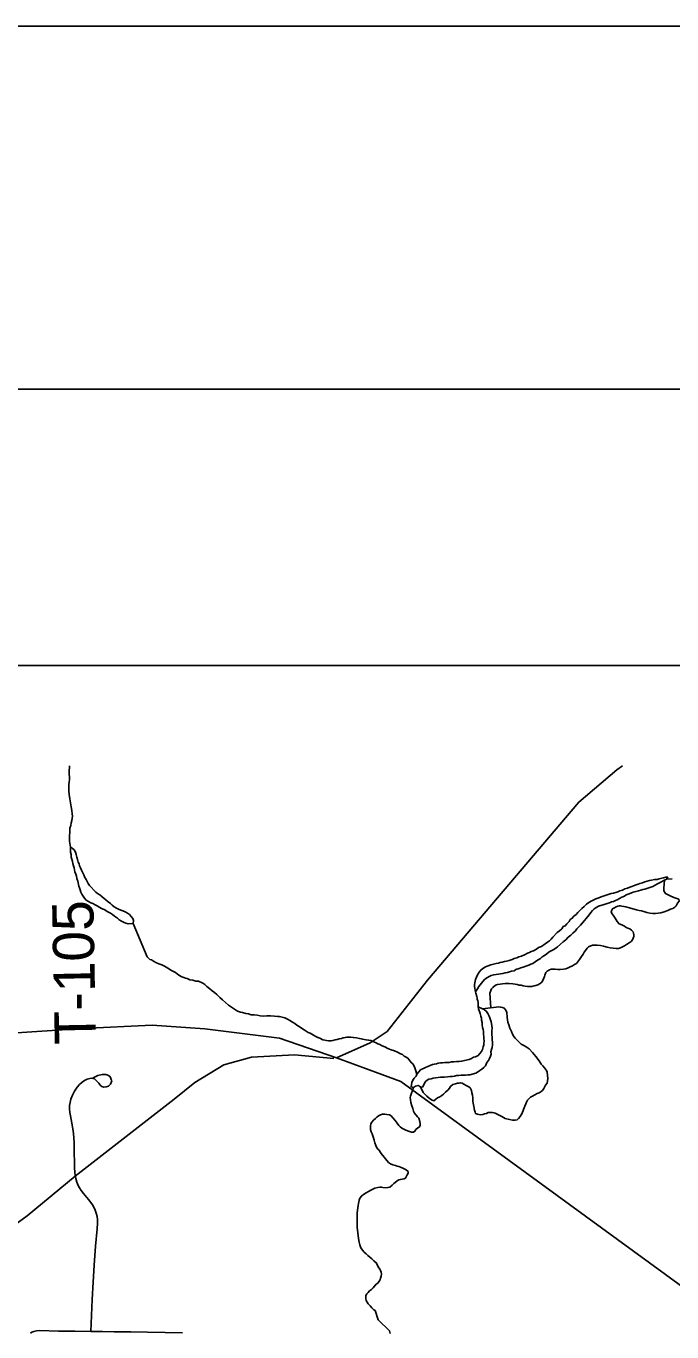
# Model space of a CAD drawing. Extents: x -11.4 to 84.1, y 11.1 to 59.
# Drawn here: x 30.669 to 31.559, y 46.631 to 48.429 of the extents above; entities that cross this region are included whole.
import ezdxf

# ---------------------------------------------------------------- set-up
doc = ezdxf.new("R2010")
doc.units = 0
for name, color, linetype in [('GM_X_Major_River', 7, 'Continuous'), ('GM_X_Minor_Lake', 7, 'Continuous'), ('GM_X_Minor_River', 7, 'Continuous'), ('GM_X_Rail_Line', 7, 'Continuous'), ('GM_X_Township_Road', 7, 'Continuous'), ('GM_X_Township_Road_Text', 7, 'Continuous'), ('SH_Border', 7, 'Continuous'), ('SH_Cut_Line', 7, 'Continuous'), ('SH_Data', 7, 'Continuous')]:
    doc.layers.add(name, color=color, linetype=linetype)

msp = doc.modelspace()

# ---------------------------------------------------------------- linework, layer by layer
at = {"layer": 'GM_X_Major_River'}
for points in [[(31.5511, 47.2539), (31.5529, 47.2566), (31.5503, 47.2566), (31.5473, 47.2558), (31.5446, 47.2554), (31.5412, 47.2546), (31.5382, 47.2538), (31.5348, 47.2534), (31.5306, 47.2527), (31.5276, 47.2523), (31.5246, 47.2511), (31.5215, 47.2503), (31.5181, 47.2488), (31.5147, 47.248), (31.5121, 47.2472), (31.5094, 47.2461), (31.506, 47.2449), (31.5034, 47.2441), (31.5007, 47.243), (31.4973, 47.2418), (31.4939, 47.2406), (31.4905, 47.2391), (31.4871, 47.2379), (31.4841, 47.2368), (31.4815, 47.2356), (31.4784, 47.2348), (31.475, 47.2341), (31.4724, 47.2333), (31.4694, 47.2325), (31.4626, 47.2302), (31.4565, 47.2279), (31.4539, 47.2271), (31.4512, 47.2255), (31.4486, 47.2244), (31.4444, 47.2217), (31.441, 47.2194), (31.4377, 47.2163), (31.4346, 47.2137), (31.4316, 47.2106), (31.429, 47.2083), (31.4267, 47.2056), (31.4237, 47.2033), (31.4215, 47.2003), (31.4185, 47.1984), (31.417, 47.1957), (31.4139, 47.1927), (31.4117, 47.19), (31.409, 47.1888), (31.4072, 47.1858), (31.4038, 47.1831), (31.4008, 47.1804), (31.3947, 47.1743), (31.3925, 47.1716), (31.3899, 47.1693), (31.3872, 47.1674), (31.3842, 47.1651), (31.3789, 47.1613), (31.3751, 47.1598), (31.3721, 47.1578), (31.368, 47.1555), (31.365, 47.1544), (31.3623, 47.1532), (31.3597, 47.1521), (31.3566, 47.1505), (31.3514, 47.1482), (31.348, 47.147), (31.3453, 47.1459), (31.3415, 47.1447), (31.3385, 47.1436), (31.3344, 47.142), (31.3309, 47.1412), (31.3283, 47.1405), (31.3249, 47.1397), (31.3222, 47.1393), (31.3196, 47.1385), (31.3166, 47.1377), (31.3128, 47.1369), (31.3094, 47.1362), (31.3018, 47.1331), (31.2984, 47.1311), (31.2954, 47.1288), (31.2932, 47.1262), (31.2909, 47.1224), (31.2894, 47.1189), (31.2883, 47.1159), (31.2868, 47.1091), (31.2869, 47.1064), (31.2882, 47.0987)], [(31.5019, 47.2346), (31.5053, 47.2362), (31.5091, 47.2369), (31.5125, 47.2381), (31.5159, 47.2389), (31.5186, 47.2397), (31.5212, 47.2404), (31.5254, 47.2416), (31.5322, 47.2439), (31.5356, 47.2459), (31.539, 47.2474), (31.5416, 47.2489), (31.5484, 47.2528), (31.5511, 47.2539)], [(31.5511, 47.2539), (31.559, 47.2544)], [(31.2882, 47.0987), (31.291, 47.103), (31.2929, 47.1064), (31.2982, 47.1133), (31.3012, 47.1164), (31.3046, 47.1187), (31.3072, 47.1202), (31.3099, 47.1214), (31.3133, 47.1225), (31.3167, 47.1229), (31.3258, 47.1241), (31.3288, 47.1249), (31.3322, 47.1257), (31.3348, 47.1265), (31.3379, 47.1272), (31.3413, 47.128), (31.3439, 47.1296), (31.3481, 47.1311), (31.3507, 47.1319), (31.3537, 47.1327), (31.359, 47.1346), (31.3617, 47.1354), (31.3643, 47.1369), (31.367, 47.1381), (31.3704, 47.14), (31.3737, 47.1427), (31.3775, 47.145), (31.3802, 47.1473), (31.3832, 47.1488), (31.3866, 47.1511), (31.3896, 47.1538), (31.3949, 47.1569), (31.3986, 47.1588), (31.4013, 47.1607), (31.4088, 47.1676), (31.4126, 47.1706), (31.416, 47.1741), (31.4194, 47.1768), (31.4224, 47.1798), (31.4261, 47.1829), (31.4276, 47.1855), (31.4303, 47.1882), (31.4329, 47.1909), (31.4355, 47.1939), (31.4385, 47.197), (31.4408, 47.1997), (31.4445, 47.205), (31.4468, 47.2081), (31.4491, 47.2107), (31.4517, 47.2134), (31.4551, 47.2157), (31.4577, 47.2169), (31.4653, 47.2192), (31.4695, 47.2204), (31.4729, 47.2215), (31.4755, 47.2227), (31.4781, 47.2231)], [(31.4781, 47.2231), (31.4808, 47.2246), (31.4834, 47.2258), (31.4865, 47.2273), (31.4895, 47.2292), (31.4932, 47.2308), (31.4959, 47.2323), (31.4985, 47.2335), (31.5019, 47.2346)], [(31.2882, 47.0987), (31.2884, 47.0969), (31.29, 47.0924), (31.2904, 47.0905), (31.2904, 47.0886), (31.2912, 47.0863), (31.2916, 47.0844), (31.2916, 47.0825), (31.2917, 47.0784)], [(31.2917, 47.0784), (31.2924, 47.0757), (31.2947, 47.0689), (31.2955, 47.0655), (31.2962, 47.0628), (31.2966, 47.0598), (31.2974, 47.0568), (31.2975, 47.0533), (31.2979, 47.0496), (31.2986, 47.0469), (31.299, 47.0442), (31.2991, 47.0405), (31.2995, 47.037), (31.2998, 47.0344), (31.2999, 47.031), (31.2995, 47.0283), (31.2995, 47.0257), (31.2988, 47.023), (31.2977, 47.0196), (31.2962, 47.0169), (31.2943, 47.0139), (31.2917, 47.0112), (31.2883, 47.0096), (31.2856, 47.0089), (31.2826, 47.0073), (31.2792, 47.0058)], [(31.3088, 47.0603), (31.308, 47.0629), (31.3068, 47.0656), (31.3053, 47.069), (31.3034, 47.072), (31.3003, 47.0746), (31.2977, 47.0757), (31.2917, 47.0784)], [(31.2029, 46.9673), (31.2056, 46.9692), (31.209, 46.97), (31.2124, 46.9681), (31.2151, 46.9678), (31.2169, 46.9708), (31.2184, 46.9739), (31.2203, 46.9765), (31.2237, 46.9785), (31.2271, 46.9792), (31.2298, 46.98), (31.24, 46.9812), (31.2426, 46.9812), (31.2453, 46.9816), (31.2494, 46.982), (31.2528, 46.9825), (31.2566, 46.9825), (31.2593, 46.9829), (31.2619, 46.9837), (31.265, 46.9837), (31.2684, 46.9841), (31.2744, 46.9841), (31.2778, 46.9845), (31.2805, 46.9845), (31.2884, 46.9869), (31.2911, 46.9884), (31.2941, 46.9907), (31.2967, 46.9926), (31.2994, 46.9949), (31.302, 46.9972), (31.3039, 47.0014), (31.3061, 47.0041), (31.3076, 47.0071), (31.3087, 47.0105), (31.3095, 47.0132), (31.3094, 47.0162), (31.3102, 47.0197), (31.3109, 47.0223), (31.3117, 47.0261), (31.3116, 47.0295), (31.3112, 47.0329), (31.3112, 47.0364), (31.3108, 47.0398), (31.3108, 47.0432), (31.3108, 47.0458), (31.3111, 47.0485), (31.3107, 47.0523), (31.3099, 47.0576), (31.3088, 47.0603)], [(31.2792, 47.0058), (31.269, 47.0034), (31.2656, 47.003), (31.2622, 47.003), (31.2584, 47.0026), (31.255, 47.0026), (31.252, 47.0018), (31.2493, 47.0014), (31.2459, 47.0014), (31.2429, 47.001), (31.2398, 47.001), (31.2368, 47.0006), (31.2342, 46.9998), (31.2315, 46.9994), (31.2289, 46.9986), (31.2258, 46.9974), (31.2232, 46.9967), (31.2194, 46.9947), (31.2126, 46.9913), (31.21, 46.9886), (31.2074, 46.9856), (31.2062, 46.9829), (31.2036, 46.9798), (31.2017, 46.9772), (31.2006, 46.9741), (31.1999, 46.9715), (31.1995, 46.968), (31.2029, 46.9673)], [(31.1523, 46.9265), (31.1545, 46.9281), (31.1572, 46.9296), (31.1602, 46.9304), (31.1632, 46.9304), (31.1659, 46.9301), (31.1697, 46.9294), (31.172, 46.9279), (31.1743, 46.9252), (31.1774, 46.9215), (31.1801, 46.9181), (31.1824, 46.915), (31.1844, 46.9132), (31.1867, 46.9113), (31.1893, 46.9098), (31.1924, 46.9083), (31.1958, 46.9068), (31.2, 46.9057), (31.2027, 46.9057), (31.2046, 46.9069), (31.2061, 46.9092), (31.2087, 46.9115), (31.2106, 46.9127), (31.2117, 46.915), (31.2117, 46.9169), (31.2113, 46.9203), (31.2101, 46.9248), (31.2081, 46.9267), (31.2043, 46.932), (31.2027, 46.9346), (31.2016, 46.938), (31.2004, 46.9418), (31.1992, 46.9464), (31.1984, 46.9502), (31.198, 46.9532), (31.1987, 46.9551), (31.2029, 46.9673)], [(31.154, 46.6474), (31.15, 46.66), (31.1481, 46.6611), (31.1454, 46.6637), (31.1431, 46.6664), (31.1404, 46.669), (31.1389, 46.6713), (31.1377, 46.6739), (31.1373, 46.6766), (31.1369, 46.6785), (31.1372, 46.6808), (31.1384, 46.6831), (31.1402, 46.685), (31.1421, 46.6869), (31.1448, 46.6888), (31.1474, 46.6911), (31.1515, 46.6961), (31.1534, 46.6977), (31.1553, 46.7003), (31.1568, 46.7023), (31.1575, 46.7045), (31.1582, 46.7072), (31.1586, 46.7099), (31.1582, 46.7129), (31.1574, 46.7152), (31.1562, 46.7171), (31.1539, 46.7201), (31.1519, 46.7254), (31.1481, 46.7284), (31.1454, 46.7314), (31.1427, 46.7337), (31.14, 46.7359), (31.1377, 46.7382), (31.135, 46.7404), (31.1327, 46.7431), (31.1304, 46.7465), (31.1288, 46.7503), (31.1277, 46.754), (31.1268, 46.759), (31.1251, 46.7749), (31.1253, 46.7943), (31.1256, 46.7981), (31.1267, 46.8046), (31.127, 46.8073), (31.1274, 46.8096), (31.1281, 46.8122), (31.1289, 46.8149), (31.1315, 46.818), (31.1341, 46.8199), (31.1375, 46.8222), (31.1409, 46.8241), (31.1451, 46.8261), (31.1496, 46.8284), (31.1538, 46.8296), (31.1564, 46.83), (31.1583, 46.83), (31.1606, 46.8293), (31.1644, 46.8289), (31.1675, 46.8293), (31.1701, 46.8301), (31.1735, 46.8328), (31.1758, 46.8351), (31.1776, 46.8363), (31.1803, 46.8386), (31.1825, 46.8398), (31.1848, 46.8405), (31.1871, 46.8409), (31.1897, 46.8414), (31.1916, 46.8425), (31.1939, 46.8467), (31.1954, 46.849), (31.1953, 46.8513), (31.1926, 46.8539), (31.1881, 46.8562), (31.185, 46.8573), (31.1827, 46.8584), (31.1804, 46.8588), (31.1778, 46.8595), (31.1743, 46.8606), (31.1709, 46.8621), (31.1682, 46.864), (31.1582, 46.8764), (31.1551, 46.8813), (31.1528, 46.8832), (31.1508, 46.8874), (31.1496, 46.8908), (31.1485, 46.8946), (31.1473, 46.8991), (31.1457, 46.9033), (31.1445, 46.9063), (31.1437, 46.9093), (31.1437, 46.912), (31.1437, 46.9143), (31.144, 46.9173), (31.1455, 46.9196), (31.1478, 46.9223), (31.1504, 46.9246), (31.1523, 46.9265)], [(31.1704, 46.6283), (31.1696, 46.6321), (31.154, 46.6474)]]:
    msp.add_lwpolyline(points, dxfattribs=at)
at = {"layer": 'GM_X_Minor_Lake'}
for points in [[(30.7302, 47.2991), (30.7302, 47.298), (30.7302, 47.2912), (30.731, 47.2878), (30.7314, 47.2844), (30.7322, 47.2817), (30.7329, 47.2783), (30.7337, 47.2757), (30.7345, 47.2723), (30.7353, 47.2696), (30.7357, 47.267), (30.7364, 47.2643), (30.7376, 47.2609), (30.7384, 47.2582), (30.7392, 47.2548), (30.7403, 47.2514), (30.7419, 47.2446), (30.7427, 47.242), (30.7438, 47.2393), (30.7446, 47.2363), (30.7461, 47.2336), (30.7477, 47.2306), (30.7496, 47.228), (30.7519, 47.2253), (30.7553, 47.2234), (30.7583, 47.2216), (30.761, 47.2205), (30.7644, 47.2186), (30.7671, 47.2171), (30.7705, 47.2152), (30.7732, 47.2137), (30.7766, 47.2122), (30.7819, 47.2092), (30.7853, 47.207), (30.788, 47.2055), (30.7907, 47.2032), (30.7948, 47.2002), (30.7975, 47.1979), (30.8006, 47.1964), (30.804, 47.1946), (30.8066, 47.1934), (30.8097, 47.1927), (30.8168, 47.1928)], [(30.7652, 47.236), (30.7563, 47.2455), (30.7544, 47.2481), (30.7532, 47.2508), (30.7517, 47.2538), (30.7498, 47.2564), (30.7486, 47.2602), (30.7455, 47.2663), (30.744, 47.2697), (30.7428, 47.2723), (30.7421, 47.275), (30.7409, 47.2776), (30.7401, 47.281), (30.739, 47.2844), (30.7382, 47.2878), (30.737, 47.2913), (30.7355, 47.2943), (30.7324, 47.2969), (30.7302, 47.2991)], [(30.8168, 47.1928), (30.8172, 47.1969), (30.8161, 47.2), (30.8138, 47.2026), (30.8115, 47.2056), (30.8088, 47.2071), (30.8058, 47.209), (30.8024, 47.2105), (30.7997, 47.2112), (30.7963, 47.2127), (30.7936, 47.2142), (30.7906, 47.2161), (30.7879, 47.2184), (30.7852, 47.2206), (30.7822, 47.2229), (30.7791, 47.2255), (30.7765, 47.2274), (30.7738, 47.2296), (30.7708, 47.2323), (30.7673, 47.2342), (30.7652, 47.236)]]:
    msp.add_lwpolyline(points, dxfattribs=at)
at = {"layer": 'GM_X_Minor_River'}
for points in [[(30.7289, 47.4103), (30.7289, 47.4082), (30.7286, 47.4033), (30.7286, 47.3987)], [(30.7286, 47.3987), (30.7287, 47.3945), (30.7287, 47.3911), (30.7284, 47.3877), (30.728, 47.3843), (30.7281, 47.3804), (30.7281, 47.3759), (30.7286, 47.3706), (30.7294, 47.3645), (30.7302, 47.3592), (30.7311, 47.3535), (30.7319, 47.3485), (30.7327, 47.344), (30.7331, 47.3406), (30.7328, 47.3379), (30.732, 47.3349), (30.7313, 47.3314), (30.7306, 47.328), (30.7295, 47.3242), (30.7292, 47.3211), (30.7292, 47.3181), (30.7289, 47.3135), (30.7289, 47.309), (30.7289, 47.3063), (30.7302, 47.298)], [(31.5322, 47.2067), (31.536, 47.2068), (31.5398, 47.2072), (31.5436, 47.2076), (31.5478, 47.2091), (31.5531, 47.2107), (31.5568, 47.2127), (31.5599, 47.2138), (31.5625, 47.2154), (31.5644, 47.2173), (31.5655, 47.2192), (31.5666, 47.2211), (31.5685, 47.2238), (31.5681, 47.2265), (31.5654, 47.2272), (31.5612, 47.2287), (31.5563, 47.2309), (31.5524, 47.2328), (31.5498, 47.2343), (31.5474, 47.238), (31.5474, 47.2399), (31.5474, 47.2418), (31.5484, 47.2528)], [(31.3094, 47.0768), (31.3081, 47.0969), (31.3091, 47.1007), (31.3103, 47.103), (31.3118, 47.1049), (31.3155, 47.108), (31.3186, 47.1092), (31.3292, 47.1104), (31.3345, 47.1105), (31.3395, 47.1101), (31.3429, 47.1094), (31.3455, 47.109), (31.3482, 47.1083), (31.3509, 47.108), (31.3539, 47.1072), (31.3566, 47.1065), (31.3596, 47.1061), (31.3627, 47.1062), (31.3657, 47.1062), (31.3688, 47.107), (31.3714, 47.1074), (31.3741, 47.1086), (31.3771, 47.1105), (31.3793, 47.1124), (31.3808, 47.1143), (31.3819, 47.117), (31.3831, 47.1201), (31.3838, 47.122), (31.3849, 47.1254), (31.3868, 47.1273), (31.3902, 47.1293), (31.3924, 47.13), (31.3947, 47.1301), (31.3981, 47.1301), (31.4016, 47.1298), (31.4046, 47.1298), (31.4092, 47.1302), (31.4126, 47.1306), (31.4156, 47.1318), (31.4186, 47.1333), (31.4217, 47.1349), (31.4247, 47.1364), (31.4273, 47.138), (31.4314, 47.1434), (31.4341, 47.1476), (31.4363, 47.1506), (31.4378, 47.1537), (31.4397, 47.156), (31.4419, 47.159), (31.4438, 47.161), (31.4491, 47.1633), (31.4521, 47.1633), (31.4559, 47.163), (31.4601, 47.1627), (31.4643, 47.1619), (31.4696, 47.1605), (31.4738, 47.1594), (31.478, 47.159), (31.4818, 47.1587), (31.4852, 47.1587), (31.4879, 47.1595), (31.4905, 47.1607), (31.4936, 47.1622), (31.4962, 47.1642), (31.4996, 47.1665), (31.5026, 47.1684), (31.5045, 47.1703), (31.5063, 47.1749), (31.5063, 47.1776), (31.5059, 47.1798), (31.5051, 47.1817), (31.5032, 47.184), (31.5009, 47.1855), (31.4982, 47.1866), (31.4959, 47.1877), (31.4933, 47.1892), (31.4898, 47.1911), (31.486, 47.1926), (31.4833, 47.1956), (31.4806, 47.2005), (31.4779, 47.2043), (31.4759, 47.2069), (31.4748, 47.2092), (31.4759, 47.2115), (31.477, 47.2134), (31.4789, 47.2142), (31.4819, 47.2161), (31.4842, 47.2169), (31.4861, 47.2173), (31.488, 47.2173), (31.4899, 47.2169), (31.4926, 47.2166), (31.4952, 47.2158), (31.4983, 47.2151), (31.5101, 47.2118), (31.5135, 47.2111), (31.5166, 47.2104), (31.52, 47.2093), (31.5242, 47.2082), (31.5284, 47.2074), (31.5322, 47.2067)], [(30.8168, 47.1928), (30.8361, 47.1469), (30.8396, 47.1436), (30.8418, 47.1428), (30.8445, 47.1413), (30.8476, 47.1394), (30.8518, 47.1376), (30.856, 47.1361), (30.8598, 47.1342), (30.8644, 47.1316), (30.8694, 47.1283), (30.8747, 47.1253), (30.8797, 47.1219), (30.8835, 47.1197), (30.8862, 47.1185), (30.8885, 47.1178), (30.8908, 47.1171), (30.8946, 47.1156), (30.8988, 47.1149), (30.903, 47.1138), (30.9068, 47.1134), (30.9125, 47.1108), (30.9152, 47.1089), (30.9179, 47.1063), (30.9221, 47.1029), (30.9256, 47.1003), (30.9287, 47.0981), (30.9317, 47.095), (30.936, 47.0913), (30.9398, 47.0879), (30.9436, 47.0841), (30.9479, 47.0804), (30.9521, 47.0778), (30.9548, 47.0759), (30.9574, 47.074), (30.9605, 47.0721), (30.9643, 47.071), (30.9674, 47.0703), (30.9716, 47.0692), (30.9754, 47.0685), (30.9792, 47.0674), (30.9834, 47.067), (30.9876, 47.0667), (30.9917, 47.066), (30.9963, 47.0656), (31.0009, 47.0657), (31.0058, 47.0657), (31.0115, 47.0654), (31.0153, 47.0651), (31.018, 47.0647), (31.0218, 47.064), (31.0256, 47.0629), (31.0291, 47.0614), (31.0325, 47.0595), (31.0359, 47.0573), (31.0394, 47.0551), (31.0421, 47.0532), (31.0444, 47.0517), (31.0478, 47.0494), (31.0497, 47.0479), (31.052, 47.0464), (31.0547, 47.0446), (31.0578, 47.0431), (31.0605, 47.042), (31.0627, 47.0408), (31.065, 47.0393), (31.0681, 47.0375), (31.0708, 47.036), (31.0738, 47.0349), (31.078, 47.033), (31.0857, 47.0312), (31.0876, 47.0312), (31.0895, 47.0316), (31.0917, 47.032), (31.0948, 47.0328), (31.0974, 47.0332), (31.1005, 47.034), (31.1035, 47.0348), (31.1058, 47.0356), (31.1088, 47.036), (31.1107, 47.0364), (31.1134, 47.0364), (31.1164, 47.0364), (31.1198, 47.0361), (31.124, 47.0354), (31.1282, 47.0346), (31.1328, 47.0335), (31.1373, 47.0328), (31.1412, 47.0321), (31.1442, 47.0318), (31.1473, 47.0307), (31.1492, 47.0295), (31.1511, 47.0288), (31.1538, 47.0273), (31.1564, 47.0262), (31.1595, 47.0247), (31.1633, 47.0232), (31.1675, 47.021)], [(31.3312, 47.0705), (31.33, 47.0735), (31.3277, 47.0762), (31.3254, 47.0773), (31.3227, 47.078), (31.3201, 47.0784), (31.2977, 47.0757)], [(31.2124, 46.9681), (31.2161, 46.9602), (31.2177, 46.9584), (31.2211, 46.955), (31.225, 46.952), (31.2284, 46.9497), (31.2307, 46.949), (31.2337, 46.9509), (31.236, 46.9528), (31.239, 46.9544), (31.2416, 46.9559), (31.2439, 46.9579), (31.2469, 46.9605), (31.2503, 46.964), (31.2522, 46.9663), (31.2537, 46.9686), (31.257, 46.9713), (31.2605, 46.9721), (31.2635, 46.9729), (31.2658, 46.9733), (31.2677, 46.9737), (31.27, 46.9729), (31.2722, 46.9718), (31.2753, 46.97), (31.2788, 46.9681), (31.2807, 46.9666), (31.2815, 46.9647), (31.2826, 46.9628), (31.283, 46.9598), (31.2838, 46.9564), (31.2843, 46.9529), (31.2847, 46.9484), (31.2867, 46.9358), (31.2875, 46.9332), (31.2883, 46.9313), (31.291, 46.9302), (31.2948, 46.9295), (31.2982, 46.9299), (31.3005, 46.9307), (31.3035, 46.9315), (31.3058, 46.9326), (31.3096, 46.9327), (31.3115, 46.9327), (31.3134, 46.9323), (31.3153, 46.9316), (31.318, 46.9305), (31.3206, 46.929), (31.3245, 46.9271), (31.3291, 46.9245), (31.3352, 46.923), (31.3393, 46.9223), (31.3428, 46.9223), (31.3454, 46.9227), (31.3473, 46.9243), (31.3496, 46.9273), (31.3522, 46.9319), (31.3544, 46.9369), (31.3562, 46.9415), (31.3577, 46.9445), (31.3585, 46.9468), (31.3599, 46.9499), (31.3618, 46.9514), (31.3641, 46.9537), (31.3667, 46.9553), (31.3701, 46.9572), (31.3731, 46.9588), (31.3758, 46.9599), (31.3784, 46.9615), (31.3803, 46.963), (31.3822, 46.9657), (31.3844, 46.9703), (31.3867, 46.9733), (31.3874, 46.9764), (31.3877, 46.9794), (31.3869, 46.9882), (31.3861, 46.9904), (31.3834, 46.9942), (31.3811, 46.9969), (31.3787, 46.9995), (31.3757, 47.004), (31.3714, 47.0097), (31.3668, 47.0153), (31.3622, 47.0202), (31.3579, 47.0232), (31.3549, 47.0251), (31.353, 47.0259), (31.3511, 47.027), (31.3476, 47.0304), (31.3449, 47.0326), (31.343, 47.0353), (31.3411, 47.0375), (31.3391, 47.0405), (31.3376, 47.0443), (31.3356, 47.0489), (31.334, 47.0534), (31.3325, 47.0572), (31.332, 47.0602), (31.3316, 47.0637), (31.3316, 47.0659), (31.3312, 47.0686), (31.3312, 47.0705)], [(31.1675, 47.021), (31.1721, 47.0191), (31.1767, 47.0176), (31.1809, 47.0158), (31.1847, 47.0135), (31.1878, 47.0124), (31.1901, 47.0105), (31.1935, 47.0083), (31.1954, 47.0072), (31.1977, 47.0038), (31.2001, 47.0011), (31.202, 46.9996), (31.2039, 46.9955), (31.2055, 46.9917), (31.2074, 46.9856)]]:
    msp.add_lwpolyline(points, dxfattribs=at)
at = {"layer": 'GM_X_Rail_Line'}
for points in [[(31.0967, 47.0078), (31.143, 47.0286), (31.1663, 47.0444), (31.2219, 47.1151), (31.4304, 47.3603), (31.483, 47.4044), (31.4905, 47.4103)], [(31.0967, 47.0078), (31.0181, 47.0352), (30.9155, 47.0479), (30.8426, 47.0531), (30.747, 47.0485), (30.6422, 47.0415), (30.4765, 47.034), (30.3404, 47.0288), (30.1476, 47.0317), (29.9217, 47.0282)], [(30.2666, 46.6209), (30.3227, 46.6366), (30.3901, 46.6534), (30.4774, 46.6821), (30.5248, 46.6971), (30.5853, 46.7284), (30.6706, 46.7906), (30.7367, 46.8449), (30.8732, 46.951), (30.9016, 46.9742), (30.9417, 46.9985), (30.9797, 47.009), (31.0386, 47.0121), (31.093, 47.0073)], [(31.0967, 47.0078), (31.1415, 46.9915), (31.1854, 46.9755), (31.6329, 46.6491), (31.7767, 46.5321), (31.9158, 46.4151), (32.0342, 46.299), (32.0917, 46.2478), (32.1332, 46.2197), (32.5505, 46.0267), (32.7642, 45.9257), (32.9065, 45.8617), (32.9839, 45.8133), (33.019, 45.784), (33.0454, 45.7608)]]:
    msp.add_lwpolyline(points, dxfattribs=at)
at = {"layer": 'GM_X_Township_Road'}
for points in [[(30.7585, 46.6311), (30.7593, 46.6532), (30.7601, 46.6753), (30.7616, 46.6989), (30.7631, 46.7226), (30.7648, 46.7488), (30.767, 46.7727), (30.7675, 46.7803), (30.7674, 46.7852), (30.7668, 46.7896), (30.7657, 46.794), (30.7644, 46.7984), (30.7626, 46.8025), (30.7607, 46.8056), (30.7585, 46.8088), (30.755, 46.813), (30.7481, 46.8213), (30.7452, 46.8254), (30.7429, 46.829), (30.741, 46.8323), (30.7391, 46.8366), (30.7375, 46.8416), (30.7367, 46.8461), (30.7361, 46.8506), (30.7357, 46.8567), (30.7355, 46.8848), (30.7353, 46.8911), (30.7348, 46.8977), (30.7343, 46.9039), (30.7334, 46.9103), (30.732, 46.9182), (30.7301, 46.928), (30.7294, 46.9325), (30.729, 46.9373), (30.7291, 46.9422), (30.7296, 46.9463), (30.7309, 46.9512), (30.733, 46.9565), (30.7359, 46.9621), (30.7395, 46.9674), (30.7428, 46.9712), (30.7463, 46.9744), (30.7497, 46.9766), (30.7534, 46.9787), (30.7588, 46.9798), (30.7633, 46.9789), (30.7668, 46.9756), (30.7692, 46.9732), (30.7711, 46.9704), (30.7736, 46.9685), (30.7764, 46.9675), (30.7794, 46.9679), (30.7828, 46.9691), (30.7853, 46.9716), (30.7864, 46.974), (30.787, 46.9765), (30.7864, 46.9783), (30.7855, 46.9809), (30.7845, 46.9824), (30.7826, 46.9839), (30.7803, 46.9848), (30.7788, 46.985), (30.7769, 46.9852), (30.7741, 46.9851), (30.7681, 46.9835), (30.7633, 46.9815), (30.7611, 46.9798)], [(30.6751, 46.6286), (30.6772, 46.6303), (30.68, 46.6313), (30.6836, 46.632), (30.6876, 46.6323), (30.7137, 46.6318), (30.7361, 46.6315), (30.7585, 46.6311), (30.7744, 46.6309), (30.7903, 46.6308), (30.8134, 46.6305), (30.8364, 46.6302), (30.8605, 46.6298), (30.8847, 46.6294)]]:
    msp.add_lwpolyline(points, dxfattribs=at)
at = {"layer": 'SH_Border'}
msp.add_lwpolyline([(4.2889, 47.9288), (36.2889, 47.9288), (36.2889, 26.9288), (4.2889, 26.9288)], close=True, dxfattribs=at)
at = {"layer": 'SH_Cut_Line'}
msp.add_lwpolyline([(2.7889, 26.4288), (36.7889, 26.4288), (36.7889, 48.4288), (2.7889, 48.4288)], close=True, dxfattribs=at)
at = {"layer": 'SH_Data'}
msp.add_line((26.1653, 47.5483), (33.1653, 47.5483), dxfattribs=at)

# ---------------------------------------------------------------- texts
at = {"layer": 'GM_X_Township_Road_Text'}
msp.add_text('T-105', height=0.05682, rotation=91.1227, dxfattribs=at).set_placement((30.7655, 47.027))

doc.saveas('drawing.dxf')
